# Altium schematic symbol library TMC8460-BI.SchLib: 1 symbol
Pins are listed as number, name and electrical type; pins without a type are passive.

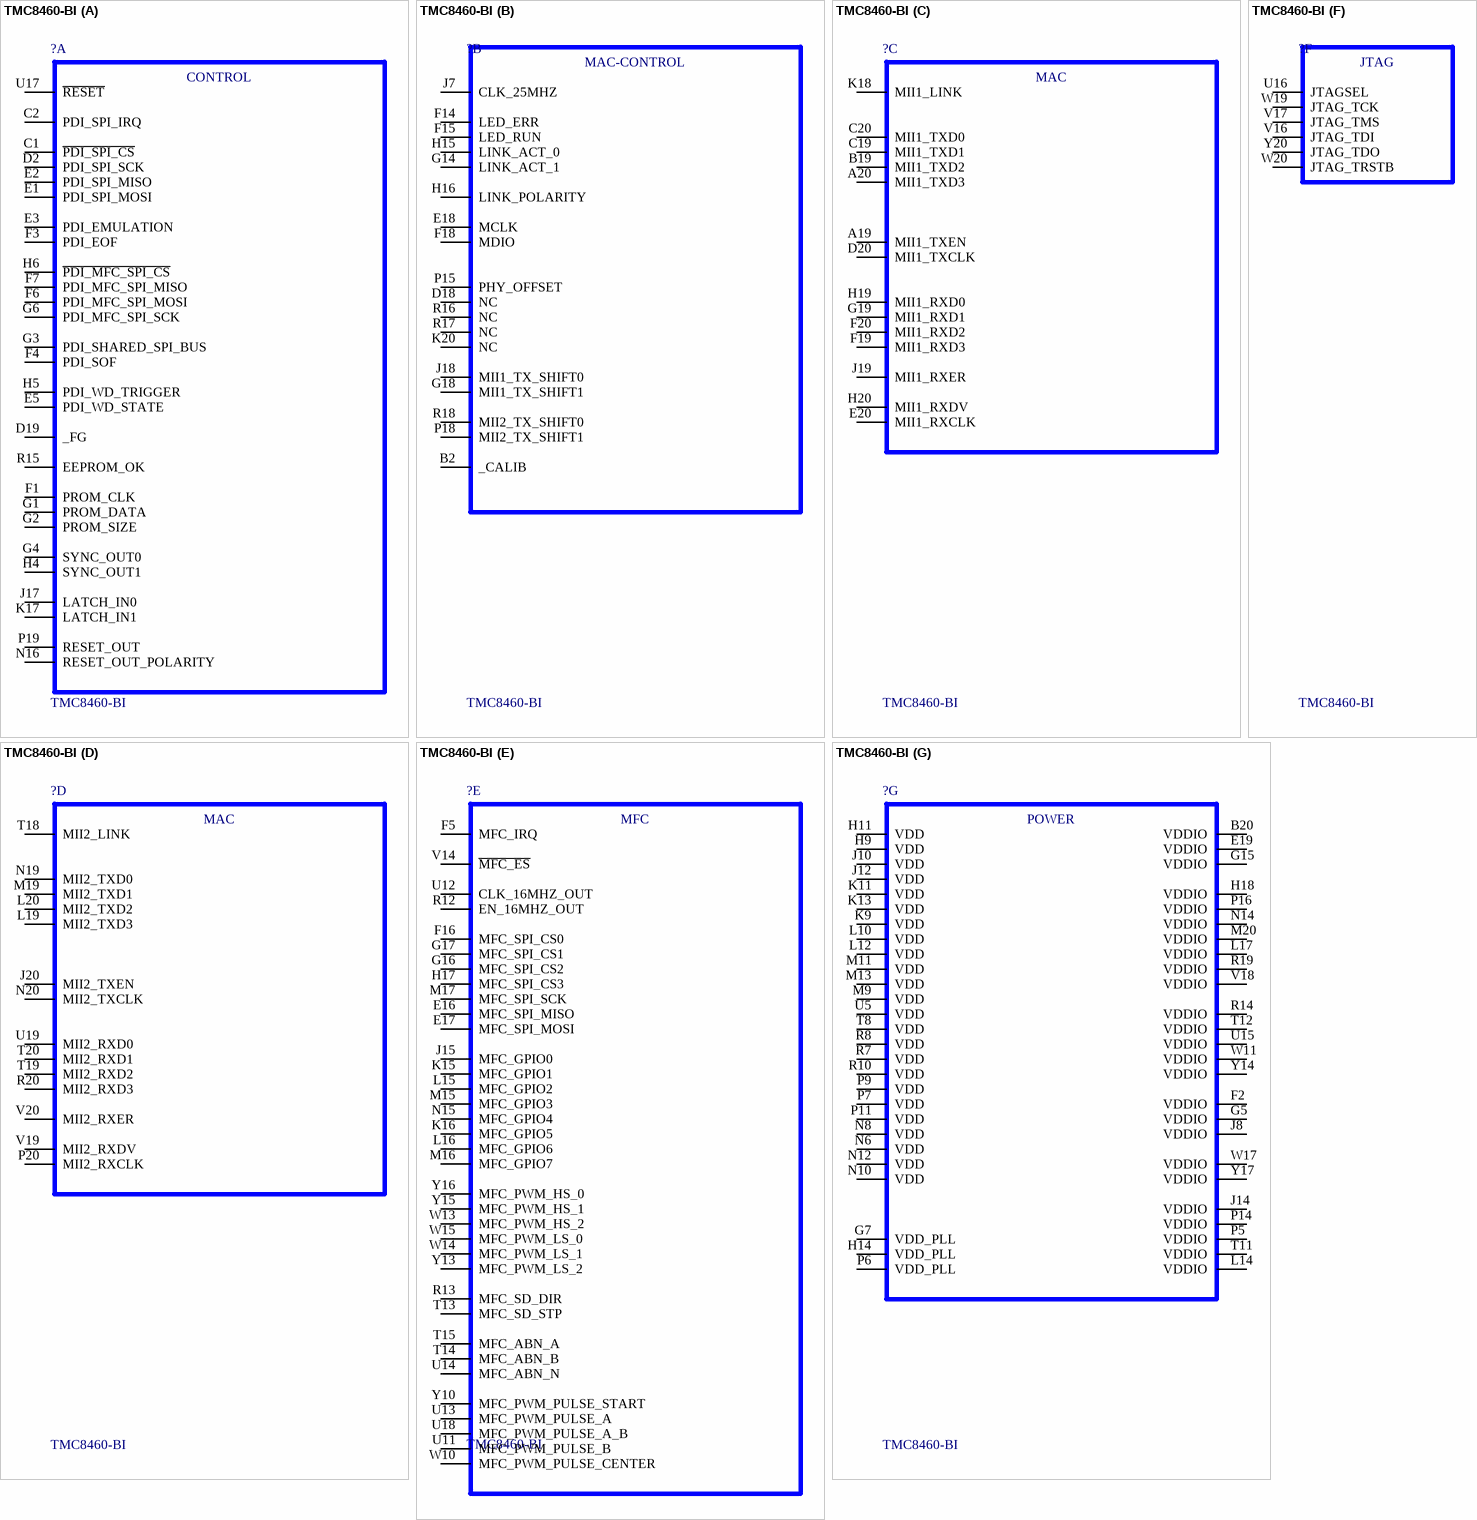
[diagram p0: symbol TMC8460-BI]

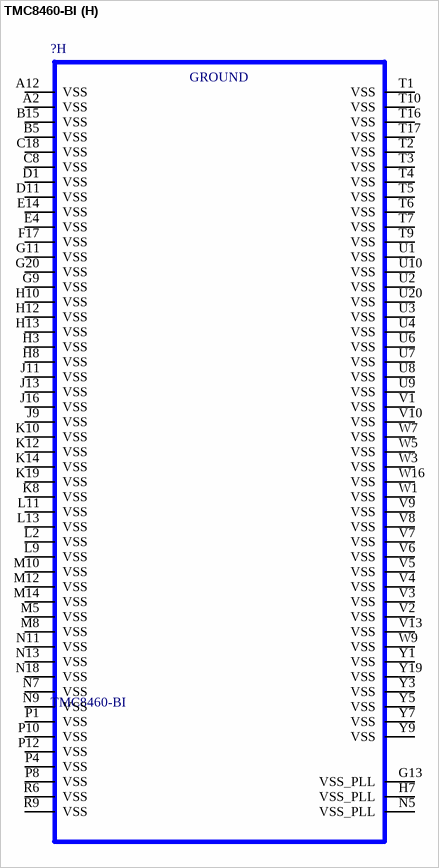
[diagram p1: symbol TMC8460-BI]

## TMC8460-BI
designator ?
ETHERCAT, IIC, PWM, RMII (EtherCAT™), SPI, SSI ;  BGA_VF400; Manufacturer: TRINAMIC; Geometry.Height: 1.51mm
footprint TMC_BGA_VF400_0.8_17X17
part A pins: C1 ~{PDI_SPI_CS}, C2 PDI_SPI_IRQ, D2 PDI_SPI_SCK, D19 _FG, E1 PDI_SPI_MOSI, E2 PDI_SPI_MISO, E3 PDI_EMULATION, E5 PDI_WD_STATE, F1 PROM_CLK, F3 PDI_EOF, F4 PDI_SOF, F6 PDI_MFC_SPI_MOSI, F7 PDI_MFC_SPI_MISO, G1 PROM_DATA, G2 PROM_SIZE, G3 PDI_SHARED_SPI_BUS, G4 SYNC_OUT0, G6 PDI_MFC_SPI_SCK, H4 SYNC_OUT1, H5 PDI_WD_TRIGGER, H6 ~{PDI_MFC_SPI_CS}, J17 LATCH_IN0, K17 LATCH_IN1, N16 RESET_OUT_POLARITY, P19 RESET_OUT, R15 EEPROM_OK, U17 ~{RESET}
part B pins: B2 _CALIB, D18 NC, E18 MCLK, F14 LED_ERR, F15 LED_RUN, F18 MDIO, G14 LINK_ACT_1, G18 MII1_TX_SHIFT1, H15 LINK_ACT_0, H16 LINK_POLARITY, J7 CLK_25MHZ, J18 MII1_TX_SHIFT0, K20 NC, P15 PHY_OFFSET, P18 MII2_TX_SHIFT1, R16 NC, R17 NC, R18 MII2_TX_SHIFT0
part C pins: A19 MII1_TXEN, A20 MII1_TXD3, B19 MII1_TXD2, C19 MII1_TXD1, C20 MII1_TXD0, D20 MII1_TXCLK, E20 MII1_RXCLK, F19 MII1_RXD3, F20 MII1_RXD2, G19 MII1_RXD1, H19 MII1_RXD0, H20 MII1_RXDV, J19 MII1_RXER, K18 MII1_LINK
part D pins: J20 MII2_TXEN, L19 MII2_TXD3, L20 MII2_TXD2, M19 MII2_TXD1, N19 MII2_TXD0, N20 MII2_TXCLK, P20 MII2_RXCLK, R20 MII2_RXD3, T18 MII2_LINK, T19 MII2_RXD2, T20 MII2_RXD1, U19 MII2_RXD0, V19 MII2_RXDV, V20 MII2_RXER
part E pins: E16 MFC_SPI_MISO, E17 MFC_SPI_MOSI, F5 MFC_IRQ, F16 MFC_SPI_CS0, G16 MFC_SPI_CS2, G17 MFC_SPI_CS1, H17 MFC_SPI_CS3, J15 MFC_GPIO0, K15 MFC_GPIO1, K16 MFC_GPIO5, L15 MFC_GPIO2, L16 MFC_GPIO6, M15 MFC_GPIO3, M16 MFC_GPIO7, M17 MFC_SPI_SCK, N15 MFC_GPIO4, R12 EN_16MHZ_OUT, R13 MFC_SD_DIR, T13 MFC_SD_STP, T14 MFC_ABN_B, T15 MFC_ABN_A, U11 MFC_PWM_PULSE_B, U12 CLK_16MHZ_OUT, U13 MFC_PWM_PULSE_A, U14 MFC_ABN_N, U18 MFC_PWM_PULSE_A_B, V14 ~{MFC_ES}, W10 MFC_PWM_PULSE_CENTER, W13 MFC_PWM_HS_2, W14 MFC_PWM_LS_1, W15 MFC_PWM_LS_0, Y10 MFC_PWM_PULSE_START, Y13 MFC_PWM_LS_2, Y15 MFC_PWM_HS_1, Y16 MFC_PWM_HS_0
part F pins: U16 JTAGSEL, V16 JTAG_TDI, V17 JTAG_TMS, W19 JTAG_TCK, W20 JTAG_TRSTB, Y20 JTAG_TDO
part G pins: B20 VDDIO, E19 VDDIO, F2 VDDIO, G5 VDDIO, G7 VDD_PLL, G15 VDDIO, H9 VDD, H11 VDD, H14 VDD_PLL, H18 VDDIO, J8 VDDIO, J10 VDD, J12 VDD, J14 VDDIO, K9 VDD, K11 VDD, K13 VDD, L10 VDD, L12 VDD, L14 VDDIO, L17 VDDIO, M9 VDD, M11 VDD, M13 VDD, M20 VDDIO, N6 VDD, N8 VDD, N10 VDD, N12 VDD, N14 VDDIO, P5 VDDIO, P6 VDD_PLL, P7 VDD, P9 VDD, P11 VDD, P14 VDDIO, P16 VDDIO, R7 VDD, R8 VDD, R10 VDD, R14 VDDIO, R19 VDDIO, T8 VDD, T11 VDDIO, T12 VDDIO, U5 VDD, U15 VDDIO, V18 VDDIO, W11 VDDIO, W17 VDDIO, Y14 VDDIO, Y17 VDDIO
part H pins: A2 VSS, A12 VSS, B5 VSS, B15 VSS, C8 VSS, C18 VSS, D1 VSS, D11 VSS, E4 VSS, E14 VSS, F17 VSS, G9 VSS, G11 VSS, G13 VSS_PLL, G20 VSS, H3 VSS, H7 VSS_PLL, H8 VSS, H10 VSS, H12 VSS, H13 VSS, J9 VSS, J11 VSS, J13 VSS, J16 VSS, K8 VSS, K10 VSS, K12 VSS, K14 VSS, K19 VSS, L2 VSS, L9 VSS, L11 VSS, L13 VSS, M5 VSS, M8 VSS, M10 VSS, M12 VSS, M14 VSS, N5 VSS_PLL, N7 VSS, N9 VSS, N11 VSS, N13 VSS, N18 VSS, P1 VSS, P4 VSS, P8 VSS, P10 VSS, P12 VSS, R6 VSS, R9 VSS, T1 VSS, T2 VSS, T3 VSS, T4 VSS, T5 VSS, T6 VSS, T7 VSS, T9 VSS, T10 VSS, T16 VSS, T17 VSS, U1 VSS, U2 VSS, U3 VSS, U4 VSS, U6 VSS, U7 VSS, U8 VSS, U9 VSS, U10 VSS, U20 VSS, V1 VSS, V2 VSS, V3 VSS, V4 VSS, V5 VSS, V6 VSS, V7 VSS, V8 VSS, V9 VSS, V10 VSS, V13 VSS, W1 VSS, W3 VSS, W5 VSS, W7 VSS, W9 VSS, W16 VSS, Y1 VSS, Y3 VSS, Y5 VSS, Y7 VSS, Y9 VSS, Y19 VSS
